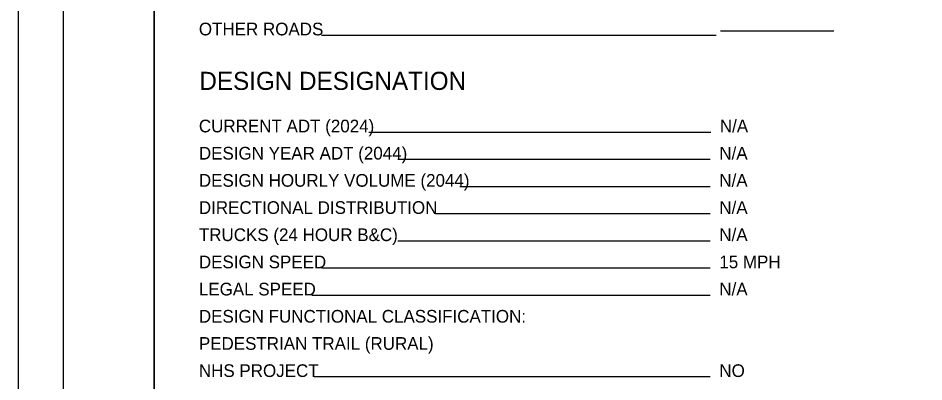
# Model space of a CAD drawing. Extents: x 0 to 34, y 0 to 22.
# Drawn here: x 0 to 9.99, y 7.05 to 11.07 of the extents above; entities that cross this region are included whole.
import ezdxf

# ---------------------------------------------------------------- set-up
doc = ezdxf.new("R2010")
doc.units = 0
for name, color, linetype in [('SH_Border', 7, 'Continuous'), ('SH_Cut_Line', 7, 'Continuous'), ('SH_Data', 7, 'Continuous'), ('SH_Text', 7, 'Continuous')]:
    doc.layers.add(name, color=color, linetype=linetype)

msp = doc.modelspace()

# ---------------------------------------------------------------- linework, layer by layer
at = {"layer": 'SH_Border'}
for points in [[(0.5, 21.5), (1.5, 21.5), (1.5, 0.5), (0.5, 0.5)], [(1.5, 21.5), (33.5, 21.5), (33.5, 0.5), (1.5, 0.5)]]:
    msp.add_lwpolyline(points, close=True, dxfattribs=at)
at = {"layer": 'SH_Cut_Line'}
msp.add_lwpolyline([(0, 0), (34, 0), (34, 22), (0, 22)], close=True, dxfattribs=at)
at = {"layer": 'SH_Data'}
for p, q in [((9, 10.9223), (7.75, 10.9223)), ((7.7, 10.8767), (3.3471, 10.8767)), ((7.6424, 9.8062), (3.871, 9.8062)), ((7.6368, 9.5062), (4.1885, 9.5062)), ((7.6368, 9.2062), (4.8723, 9.2062)), ((7.6368, 8.9062), (4.6037, 8.9062)), ((7.6368, 8.6062), (4.1885, 8.6062)), ((7.6368, 8.3062), (3.346, 8.3062)), ((7.6368, 8.0062), (3.2422, 8.0062)), ((7.6368, 7.1062), (3.2669, 7.1062))]:
    msp.add_line(p, q, dxfattribs=at)

# ---------------------------------------------------------------- texts
msp.add_text('DESIGN DESIGNATION', height=0.2, dxfattribs=at).set_placement((2, 10.2747))
at = {"layer": 'SH_Text'}
for s, p in [('OTHER ROADS', (1.9944, 10.8767)), ('CURRENT ADT (2024)', (1.9944, 9.8062)), ('N/A', (7.7424, 9.8062)), ('DESIGN YEAR ADT (2044)', (1.9944, 9.5062)), ('N/A', (7.7368, 9.5062)), ('DESIGN HOURLY VOLUME (2044)', (1.9944, 9.2062)), ('N/A', (7.7368, 9.2062)), ('DIRECTIONAL DISTRIBUTION', (1.9944, 8.9062)), ('N/A', (7.7368, 8.9062)), ('TRUCKS (24 HOUR B&C)', (1.9944, 8.6062)), ('N/A', (7.7368, 8.6062)), ('DESIGN SPEED', (1.9944, 8.3062)), ('15 MPH', (7.7368, 8.3062)), ('LEGAL SPEED', (1.9944, 8.0062)), ('N/A', (7.7368, 8.0062)), ('DESIGN FUNCTIONAL CLASSIFICATION:', (1.9944, 7.7062)), ('PEDESTRIAN TRAIL (RURAL)', (1.9944, 7.4062)), ('NHS PROJECT', (1.9944, 7.1062)), ('NO', (7.7368, 7.1062))]:
    msp.add_text(s, height=0.14, dxfattribs=at).set_placement(p)

doc.saveas('drawing.dxf')
